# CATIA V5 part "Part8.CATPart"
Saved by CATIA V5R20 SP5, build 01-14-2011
Part number: 中右
Bounding box of the stored display mesh (mm): x 40.887 to 99.851, y -5 to 5, z -150.472 to 1.581
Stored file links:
  F:\CAD\很靠后、\Part8.CATPart
  F:\CAD\很靠后、\Part7.CATPart
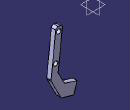
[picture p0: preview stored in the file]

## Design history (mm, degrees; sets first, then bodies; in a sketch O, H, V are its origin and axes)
Body1 (main body)
  Sketch1 on zx-plane, origin (0, 0, 0), H (-1, 0, 0), V (0, 0, 1)
    line L1 (-88.7834, 2.1431) -> (-73.8784, 0.4573)
    line L2 (-73.8784, 0.4573) -> (-83.9928, -88.9725)
    line L3 (-100.0216, -97.2234) -> (-88.7834, 2.1431)
    point P3 (-100.0216, -97.2234)
    circle A1 centre (-82.4547, -8.6365) radius 5
    point P4 (-82.4547, -8.6365)
    line L4 (-83.9928, -88.9725) -> (-100.0216, -97.2234)
    point P6 (-100.0216, -97.2234)
    radius A1 = 5
    length L1 = 15
    distance P4 L3 = 7.5
    distance P4 L1 = 10
    length L2 = 90
    length L3 = 100
    parallelism: L3 L2
    perpendicularity: L1 L2
    coincidence: P6 L3, L4 P3, P3 P6
Body2
  Pad1: profile Sketch1, direction (0, 1, 0), length 5, mirrored extent
  Sketch2 on zx-plane, origin (0, 0, 0), H (-1, 0, 0), V (0, 0, 1)
    line L1 (-83.9928, -88.9725) -> (-100.0216, -97.2234)
    point P1 (-83.9928, -88.9725)
    point P2 (-100.0216, -97.2234)
    line L2 (-100.0216, -97.2234) -> (-77.1376, -141.6793)
    line L3 (-77.1376, -141.6793) -> (-61.1088, -133.4284)
    line L4 (-61.1088, -133.4284) -> (-83.9928, -88.9725)
    reference projected point E1 (-83.9928, -88.9725) from vertex [face of Pad1 from Sketch1.L2 | end face of Pad1 | face of Pad1 from Sketch1.L4]
    reference projected point E2 (-100.0216, -97.2234) from vertex [face of Pad1 from Sketch1.L4 | end face of Pad1 | face of Pad1 from Sketch1.L3]
    distance P1 E1 = 0
    distance P2 E2 = 0
    length L2 = 50
    parallelism: L4 L2, L1 L3
    perpendicularity: L1 L2
  Pad2: profile Sketch2, direction (0, 1, 0), length 5, mirrored extent
  Fillet1: radius 5, on edge [face of Pad2 from Sketch2.L2 | face of Pad1 from Sketch1.L3]
  Fillet2: radius 5, on edge [face of Pad1 from Sketch1.L2 | face of Pad2 from Sketch2.L4]
  Fillet3: radius 5, on edge [face of Pad1 from Sketch1.L3 | face of Pad1 from Sketch1.L1]; edge [face of Pad1 from Sketch1.L1 | face of Pad1 from Sketch1.L2]
  Sketch3 on zx-plane, origin (0, 0, 0), H (-1, 0, 0), V (0, 0, 1)
    line L1 (-77.1376, -141.6793) -> (-69.5696, -116.9921)
    point P1 (-77.1376, -141.6793)
    point P2 (-69.5696, -116.9921)
    line L2 (-69.5696, -116.9921) -> (-40.8871, -125.7849)
    line L3 (-40.8871, -125.7849) -> (-48.4551, -150.4722)
    line L4 (-48.4551, -150.4722) -> (-77.1376, -141.6793)
    reference projected line E1 (-61.1088, -133.4284) -> (-83.9928, -88.9725) from edge [face of Pad2 from Sketch2.L4 | face of Pad2]
    reference projected point E2 (-77.1376, -141.6793) from vertex [face of Pad2 from Sketch2.L3 | end face of Pad2 | face of Pad2 from Sketch2.L2]
    reference projected point E3 (-83.2999, -90.3185) from vertex [face of Pad2 from Sketch2.L4 | face of Fillet2 | face of Pad2]
    distance P2 E1 = 0
    distance P1 E2 = 0
    distance P2 E3 = 30
    length L4 = 30
    parallelism: L4 L2, L1 L3
    perpendicularity: L1 L2
  Pad3: profile Sketch3, direction (0, 1, 0), length 5, mirrored extent
  Fillet4: radius 5, on edge [face of Pad3 from Sketch3.L4 | face of Pad2 from Sketch2.L2]; edge [face of Pad2 from Sketch2.L4 | face of Pad3 from Sketch3.L2]
  Sketch4 on face of Pad3, origin (0, 5, 0), H (-1, 0, 0), V (0, 0, 1)
    circle A1 centre (-89.1976, -68.2564) radius 5
    point P1 (-89.1976, -68.2564)
    reference projected line E1 (-88.7834, 2.1431) -> (-100.0216, -97.2234) from edge [face of Pad1 from Sketch1.L3 | face of Pad3]
    reference projected line E2 (-73.8784, 0.4573) -> (-88.7834, 2.1431) from edge [face of Pad1 from Sketch1.L1 | face of Pad3]
    radius A1 = 5
    distance P1 E1 = 7.5
    distance P1 E2 = 70
  Pocket1: profile Sketch4, direction (0, -1, 0), length 10, mirrored extent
